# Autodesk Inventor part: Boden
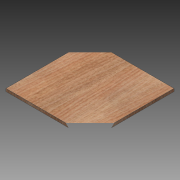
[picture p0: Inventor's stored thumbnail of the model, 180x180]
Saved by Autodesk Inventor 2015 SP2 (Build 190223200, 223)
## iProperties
Created: 2012-07
Part Number: Boden
Material: Holz (Birke)
Document SubType Name: Modeling
Designer: rYan
Mass: 495 g
Surface Area: 1920 cm^2
Volume: 900 cm^3
Density: 0.55 g/cm^3
Appearance: Birke - natur - poliert
Author: rYan
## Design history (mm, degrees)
sketch "Skizze1"
  geometry: L1 (-150, -150)-(150, -150); L2 (150, -150)-(150, 150); L3 (150, 150)-(-150, 150); L4 (-150, 150)-(-150, -150); L5 (-150, -150)-(150, 150); L6 (150, -150)-(-150, 150); 1 further point
  constraints: 12 end point, 2 midpoint, 2 parallel, 1 horizontal, 1 perpendicular
  dimensions: "d0" = 300 distance of L2.end L3.end; "d1" = 300 distance of L3.end L1.start
extrude "Extrusion1" new body sketch "Skizze1" distance "d2" = 10; taper "d3" = 0 deg
node "Volumenkörper1"
